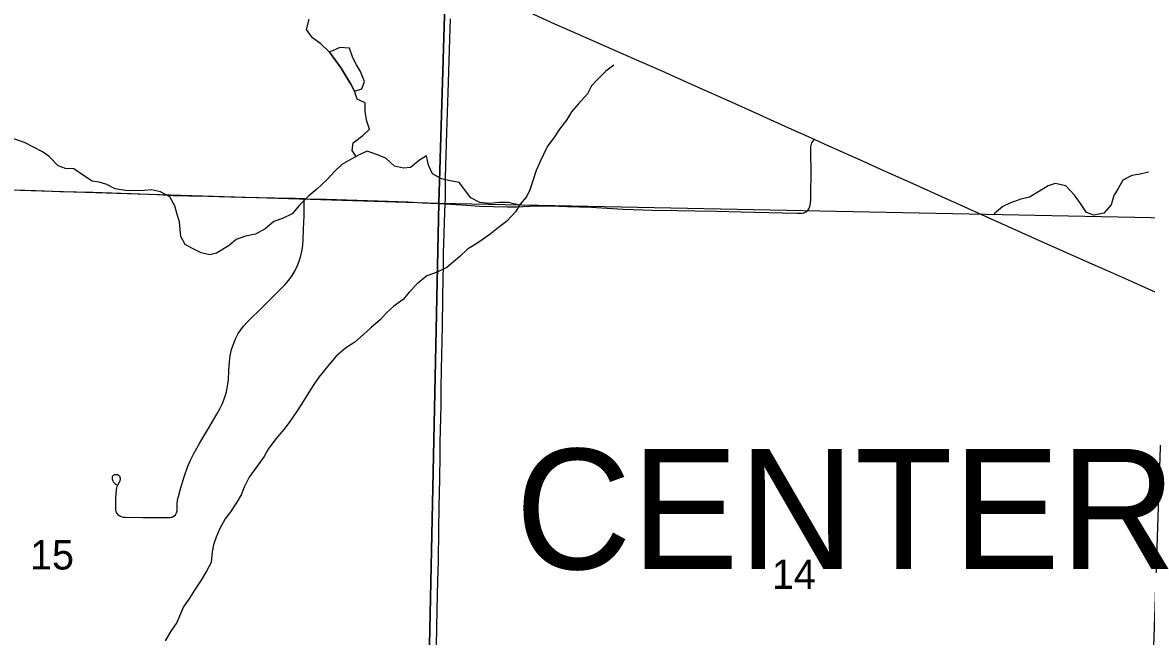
# Model space of a CAD drawing. Extents: x 0 to 34, y 0 to 22.
# Drawn here: x 4.092 to 5.686, y 19.878 to 20.749 of the extents above; entities that cross this region are included whole.
import ezdxf

# ---------------------------------------------------------------- set-up
doc = ezdxf.new("R2010")
doc.units = 0
for name, color, linetype in [('GM_X_Minor_Lake', 7, 'Continuous'), ('GM_X_Minor_River', 7, 'Continuous'), ('GM_X_Rail_Line_Text', 7, 'Continuous'), ('GM_X_Section', 7, 'Continuous'), ('GM_X_Section_Text', 7, 'Continuous'), ('GM_X_State_Route', 7, 'Continuous'), ('GM_X_Township_Road', 7, 'Continuous'), ('GM_X_Township_Text', 7, 'Continuous')]:
    doc.layers.add(name, color=color, linetype=linetype)

msp = doc.modelspace()

# ---------------------------------------------------------------- linework, layer by layer
at = {"layer": 'GM_X_Minor_Lake'}
for points in [[(4.5631, 20.6515), (4.5737, 20.6547), (4.5777, 20.6648), (4.5716, 20.679), (4.5661, 20.6886), (4.5609, 20.6986), (4.5563, 20.7123), (4.5426, 20.713), (4.5277, 20.7068)], [(4.5277, 20.7068), (4.5366, 20.6941), (4.5444, 20.6841), (4.5513, 20.6722), (4.5579, 20.6611), (4.5631, 20.6515)]]:
    msp.add_lwpolyline(points, dxfattribs=at)
at = {"layer": 'GM_X_Minor_River'}
for points in [[(4.5658, 20.5588), (4.5599, 20.5673), (4.5613, 20.5782), (4.5751, 20.5886), (4.5848, 20.5975), (4.5805, 20.6101), (4.5784, 20.6231), (4.5783, 20.6349), (4.567, 20.64), (4.5631, 20.6515), (4.5579, 20.6611), (4.5513, 20.6722), (4.5444, 20.6841), (4.5366, 20.6941), (4.5277, 20.7068), (4.5154, 20.7184), (4.5035, 20.727), (4.4953, 20.7385), (4.499, 20.7533)], [(4.9312, 20.6884), (4.9197, 20.6795), (4.9089, 20.6687), (4.8996, 20.659), (4.8937, 20.6477), (4.8805, 20.6328), (4.8712, 20.622), (4.8637, 20.61), (4.854, 20.5976), (4.8462, 20.5849), (4.8372, 20.5733), (4.8313, 20.5613), (4.8266, 20.5515), (4.821, 20.5387), (4.8162, 20.5244), (4.8118, 20.5112), (4.8074, 20.5014), (4.7981, 20.4913), (4.7919, 20.4808), (4.7787, 20.4663), (4.7675, 20.4581), (4.7556, 20.4485), (4.7456, 20.4415), (4.7352, 20.4345), (4.7237, 20.4275), (4.7129, 20.4171), (4.694, 20.4015), (4.6806, 20.3945), (4.6661, 20.3895), (4.6522, 20.378), (4.641, 20.3661), (4.6321, 20.356), (4.619, 20.3464), (4.6086, 20.3371), (4.6, 20.3274), (4.5866, 20.3159), (4.5761, 20.3062), (4.5638, 20.2954), (4.5507, 20.287), (4.5372, 20.2755), (4.5248, 20.2609), (4.5128, 20.2456), (4.5057, 20.2355), (4.4979, 20.2235), (4.4881, 20.2077), (4.4811, 20.1965), (4.4706, 20.1815), (4.4632, 20.1718), (4.4519, 20.1583), (4.441, 20.1437), (4.4351, 20.1332), (4.4254, 20.1197), (4.4141, 20.104), (4.407, 20.0897), (4.4026, 20.0788), (4.3964, 20.0687), (4.3874, 20.0548), (4.38, 20.0451), (4.3717, 20.0304), (4.367, 20.0191), (4.3633, 20.0082), (4.3616, 19.998), (4.3598, 19.9832), (4.3535, 19.9708), (4.3457, 19.9581), (4.3363, 19.9438), (4.3293, 19.9326), (4.3207, 19.9202), (4.3167, 19.9104), (4.3115, 19.898), (4.303, 19.8856), (4.2947, 19.8718)], [(4.7972, 20.4898), (4.7819, 20.4935), (4.7686, 20.4934), (4.7545, 20.4922), (4.7409, 20.4936), (4.7281, 20.4999), (4.7193, 20.5118), (4.7119, 20.5218), (4.6968, 20.5248), (4.6866, 20.5269), (4.6738, 20.5343), (4.668, 20.5462), (4.6656, 20.5595), (4.6556, 20.5533), (4.6425, 20.5433), (4.633, 20.5423), (4.6198, 20.5449), (4.6079, 20.5565), (4.5943, 20.5617), (4.5811, 20.5661), (4.5708, 20.5614), (4.5586, 20.5551), (4.5455, 20.5474), (4.5347, 20.5374), (4.5239, 20.5255), (4.5099, 20.5124), (4.4984, 20.5028), (4.4852, 20.4898), (4.4751, 20.4774), (4.461, 20.4709), (4.4488, 20.4666), (4.4364, 20.4562), (4.423, 20.4485), (4.4089, 20.4457), (4.3956, 20.441), (4.3855, 20.4325), (4.3675, 20.4218), (4.358, 20.4193), (4.3459, 20.4222), (4.3328, 20.4289), (4.323, 20.4337), (4.3171, 20.4452), (4.3162, 20.4551), (4.3153, 20.4661), (4.3117, 20.4764), (4.3085, 20.4886), (4.3012, 20.5013), (4.288, 20.5088), (4.2752, 20.5113), (4.2653, 20.5103), (4.2524, 20.5098), (4.2384, 20.5105), (4.224, 20.513), (4.212, 20.5189), (4.2011, 20.5222), (4.1912, 20.5235), (4.1778, 20.5325), (4.1654, 20.5411), (4.1533, 20.5417), (4.1431, 20.5453), (4.1305, 20.5589), (4.1208, 20.5655), (4.108, 20.5718), (4.0952, 20.5785), (4.0775, 20.5848)], [(5.6894, 20.5364), (5.6776, 20.5335), (5.6654, 20.5319), (5.6528, 20.5249), (5.6461, 20.5133), (5.6402, 20.5035), (5.6365, 20.4903), (5.6257, 20.4784), (5.6116, 20.4756), (5.6011, 20.4792), (5.593, 20.4919), (5.5841, 20.5038), (5.5722, 20.517), (5.5567, 20.5203), (5.5472, 20.5171), (5.5345, 20.5094), (5.5207, 20.5009), (5.5081, 20.4981), (5.4925, 20.4923), (5.4829, 20.4876), (5.4706, 20.4772)]]:
    msp.add_lwpolyline(points, dxfattribs=at)
at = {"layer": 'GM_X_Rail_Line_Text'}
for points in [[(4.6953, 20.9), (3.6842, 20.9), (3.6779, 20.5235), (4.6829, 20.4926)], [(5.7281, 20.9), (4.6953, 20.9), (4.6829, 20.4926), (5.7169, 20.4716)]]:
    msp.add_lwpolyline(points, close=True, dxfattribs=at)
at = {"layer": 'GM_X_Section'}
for points in [[(3.6779, 20.5235), (4.6829, 20.4926), (4.6614, 19.4847), (3.6762, 19.5163)], [(4.6829, 20.4926), (5.7169, 20.4716), (5.6833, 19.4667), (4.6614, 19.4847)]]:
    msp.add_lwpolyline(points, close=True, dxfattribs=at)
at = {"layer": 'GM_X_State_Route'}
for points in [[(4.6791, 19.8395), (4.6807, 19.9165), (4.6815, 19.9569), (4.6822, 19.9849), (4.6828, 20.0291), (4.6834, 20.0614), (4.6842, 20.1018), (4.6846, 20.1347), (4.685, 20.154), (4.6853, 20.1695), (4.6862, 20.2068), (4.6864, 20.2304), (4.6869, 20.2565), (4.6881, 20.3181), (4.6885, 20.3579), (4.6891, 20.3864), (4.6893, 20.4025), (4.6897, 20.4212), (4.6915, 20.4796), (4.6919, 20.4916), (4.6922, 20.4995), (4.6925, 20.5293), (4.6943, 20.5926), (4.6967, 20.6638), (4.6985, 20.7253), (4.6993, 20.7539)], [(4.8108, 20.7631), (4.8471, 20.7469), (4.8721, 20.7357), (4.904, 20.7218), (4.9364, 20.7076), (4.9706, 20.6925), (4.999, 20.6799), (5.0399, 20.6617), (5.1017, 20.6341), (5.1267, 20.6229), (5.1788, 20.5993), (5.2152, 20.5831), (5.2293, 20.5768), (5.2854, 20.5514), (5.3081, 20.5413), (5.3604, 20.5179), (5.3955, 20.502), (5.4221, 20.4901), (5.4578, 20.474), (5.5321, 20.4406), (5.6054, 20.408), (5.6305, 20.397), (5.669, 20.3798), (5.7077, 20.3626)]]:
    msp.add_lwpolyline(points, dxfattribs=at)
at = {"layer": 'GM_X_Township_Road'}
for points in [[(5.203, 20.4796), (5.2046, 20.4806), (5.2063, 20.4823), (5.2076, 20.4844), (5.2089, 20.4879), (5.2098, 20.4922), (5.2103, 20.4977), (5.2106, 20.5108), (5.2108, 20.5307), (5.2105, 20.5699), (5.2106, 20.5723), (5.2109, 20.5743), (5.2114, 20.5761), (5.212, 20.5781), (5.2132, 20.5801), (5.2145, 20.582), (5.2152, 20.5831)], [(3.6824, 20.5235), (3.7299, 20.5221), (3.802, 20.5199), (3.8386, 20.5188), (3.9045, 20.5166), (3.997, 20.5139), (4.0461, 20.5126), (4.0797, 20.5114), (4.112, 20.5103), (4.1461, 20.5091), (4.1921, 20.508), (4.2462, 20.5063), (4.2841, 20.5046), (4.3064, 20.5036), (4.3294, 20.503), (4.3555, 20.5023), (4.404, 20.5011), (4.4506, 20.5001), (4.4792, 20.4995), (4.4922, 20.4989)], [(4.3093, 20.0508), (4.3109, 20.0533), (4.3115, 20.0548), (4.3117, 20.0564), (4.3118, 20.0585), (4.3119, 20.065), (4.3125, 20.0719), (4.3135, 20.0767), (4.3164, 20.0875), (4.3218, 20.1047), (4.3271, 20.1194), (4.3306, 20.128), (4.3353, 20.1374), (4.344, 20.1525), (4.3568, 20.1738), (4.3682, 20.1931), (4.3724, 20.2007), (4.376, 20.2086), (4.3794, 20.2173), (4.3817, 20.2251), (4.3834, 20.233), (4.3846, 20.2422), (4.3851, 20.2553), (4.3859, 20.267), (4.3871, 20.2763), (4.389, 20.2848), (4.3921, 20.2942), (4.395, 20.3011), (4.3985, 20.3077), (4.4019, 20.3129), (4.4061, 20.3183), (4.4115, 20.3243), (4.4336, 20.3461), (4.4576, 20.3696), (4.465, 20.3771), (4.4703, 20.3833), (4.4749, 20.3899), (4.479, 20.3969), (4.4825, 20.4041), (4.485, 20.4105), (4.4872, 20.4176), (4.4891, 20.4261), (4.4902, 20.4329), (4.4907, 20.4403), (4.4912, 20.4558), (4.4917, 20.4744), (4.4921, 20.4969), (4.4922, 20.4989)], [(4.4922, 20.4989), (4.4947, 20.4988), (4.5084, 20.4983), (4.5233, 20.498), (4.6108, 20.4953), (4.6388, 20.4942), (4.6593, 20.4932), (4.6819, 20.4922)], [(4.6819, 20.4922), (4.6878, 20.4919), (4.6919, 20.4916)], [(4.6919, 20.4916), (4.707, 20.4906), (4.7225, 20.4895), (4.7405, 20.4884), (4.7601, 20.4876), (4.7804, 20.4871), (4.7933, 20.4875), (4.8212, 20.4885), (4.8399, 20.4885), (4.8654, 20.4878), (4.8989, 20.4867), (4.9442, 20.4842), (4.9865, 20.4828), (5.0213, 20.4821), (5.0461, 20.4817), (5.0772, 20.481), (5.1114, 20.4802), (5.1704, 20.4788), (5.1909, 20.4781), (5.1949, 20.4781), (5.1977, 20.4783), (5.1996, 20.4786), (5.2008, 20.4789), (5.203, 20.4796)], [(4.2282, 20.0508), (4.2269, 20.0523), (4.2258, 20.0537), (4.2251, 20.0555), (4.2249, 20.0573), (4.2249, 20.0593), (4.2248, 20.0668), (4.225, 20.0749), (4.2259, 20.0867), (4.2262, 20.0887), (4.2268, 20.091), (4.2275, 20.0925), (4.2282, 20.0938), (4.2293, 20.0957), (4.23, 20.0967), (4.2304, 20.0977), (4.2309, 20.0989), (4.2311, 20.0999), (4.2313, 20.1011), (4.2313, 20.1023), (4.2311, 20.1034), (4.2308, 20.1043), (4.2301, 20.1053), (4.2295, 20.1059), (4.2285, 20.1066), (4.2274, 20.1071), (4.2268, 20.1074), (4.2259, 20.1075), (4.2243, 20.1075), (4.2229, 20.1072), (4.222, 20.1068), (4.2209, 20.1062), (4.2202, 20.1053), (4.2198, 20.1045), (4.2196, 20.1036), (4.2196, 20.102), (4.2197, 20.1011), (4.22, 20.1002), (4.2204, 20.099), (4.2209, 20.098), (4.2214, 20.0973), (4.2218, 20.0966), (4.2223, 20.096), (4.223, 20.0953), (4.2243, 20.0943), (4.2248, 20.094), (4.2255, 20.0936), (4.2271, 20.0932)], [(4.2282, 20.0508), (4.2303, 20.0491), (4.2322, 20.0483), (4.2334, 20.0478), (4.2357, 20.0474), (4.2383, 20.0473), (4.2631, 20.047), (4.291, 20.0466), (4.2997, 20.0468), (4.3015, 20.047), (4.3034, 20.0472), (4.3045, 20.0475), (4.3057, 20.048), (4.3074, 20.049), (4.3093, 20.0508)]]:
    msp.add_lwpolyline(points, dxfattribs=at)

# ---------------------------------------------------------------- texts
at = {"layer": 'GM_X_Section_Text'}
for s, p in [('15', (4.1032, 19.9731)), ('14', (5.1552, 19.9454))]:
    msp.add_text(s, height=0.04186, rotation=0, dxfattribs=at).set_placement(p)
at = {"layer": 'GM_X_Township_Text'}
msp.add_text('CENTER', height=0.17045, rotation=0, dxfattribs=at).set_placement((4.7913, 19.9736))

doc.saveas('drawing.dxf')
